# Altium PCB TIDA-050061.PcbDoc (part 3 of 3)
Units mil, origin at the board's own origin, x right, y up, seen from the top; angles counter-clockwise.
Board outline 3950.94 x 4411.21 mil, 8 copper layers (Top Layer, Layer 1, Layer 2, Layer 3, Layer 4, Layer 5, Layer 6, Bottom Layer), stack 61.2 mil thick; 178 components, 34 nets, 398 pads, 112 vias.
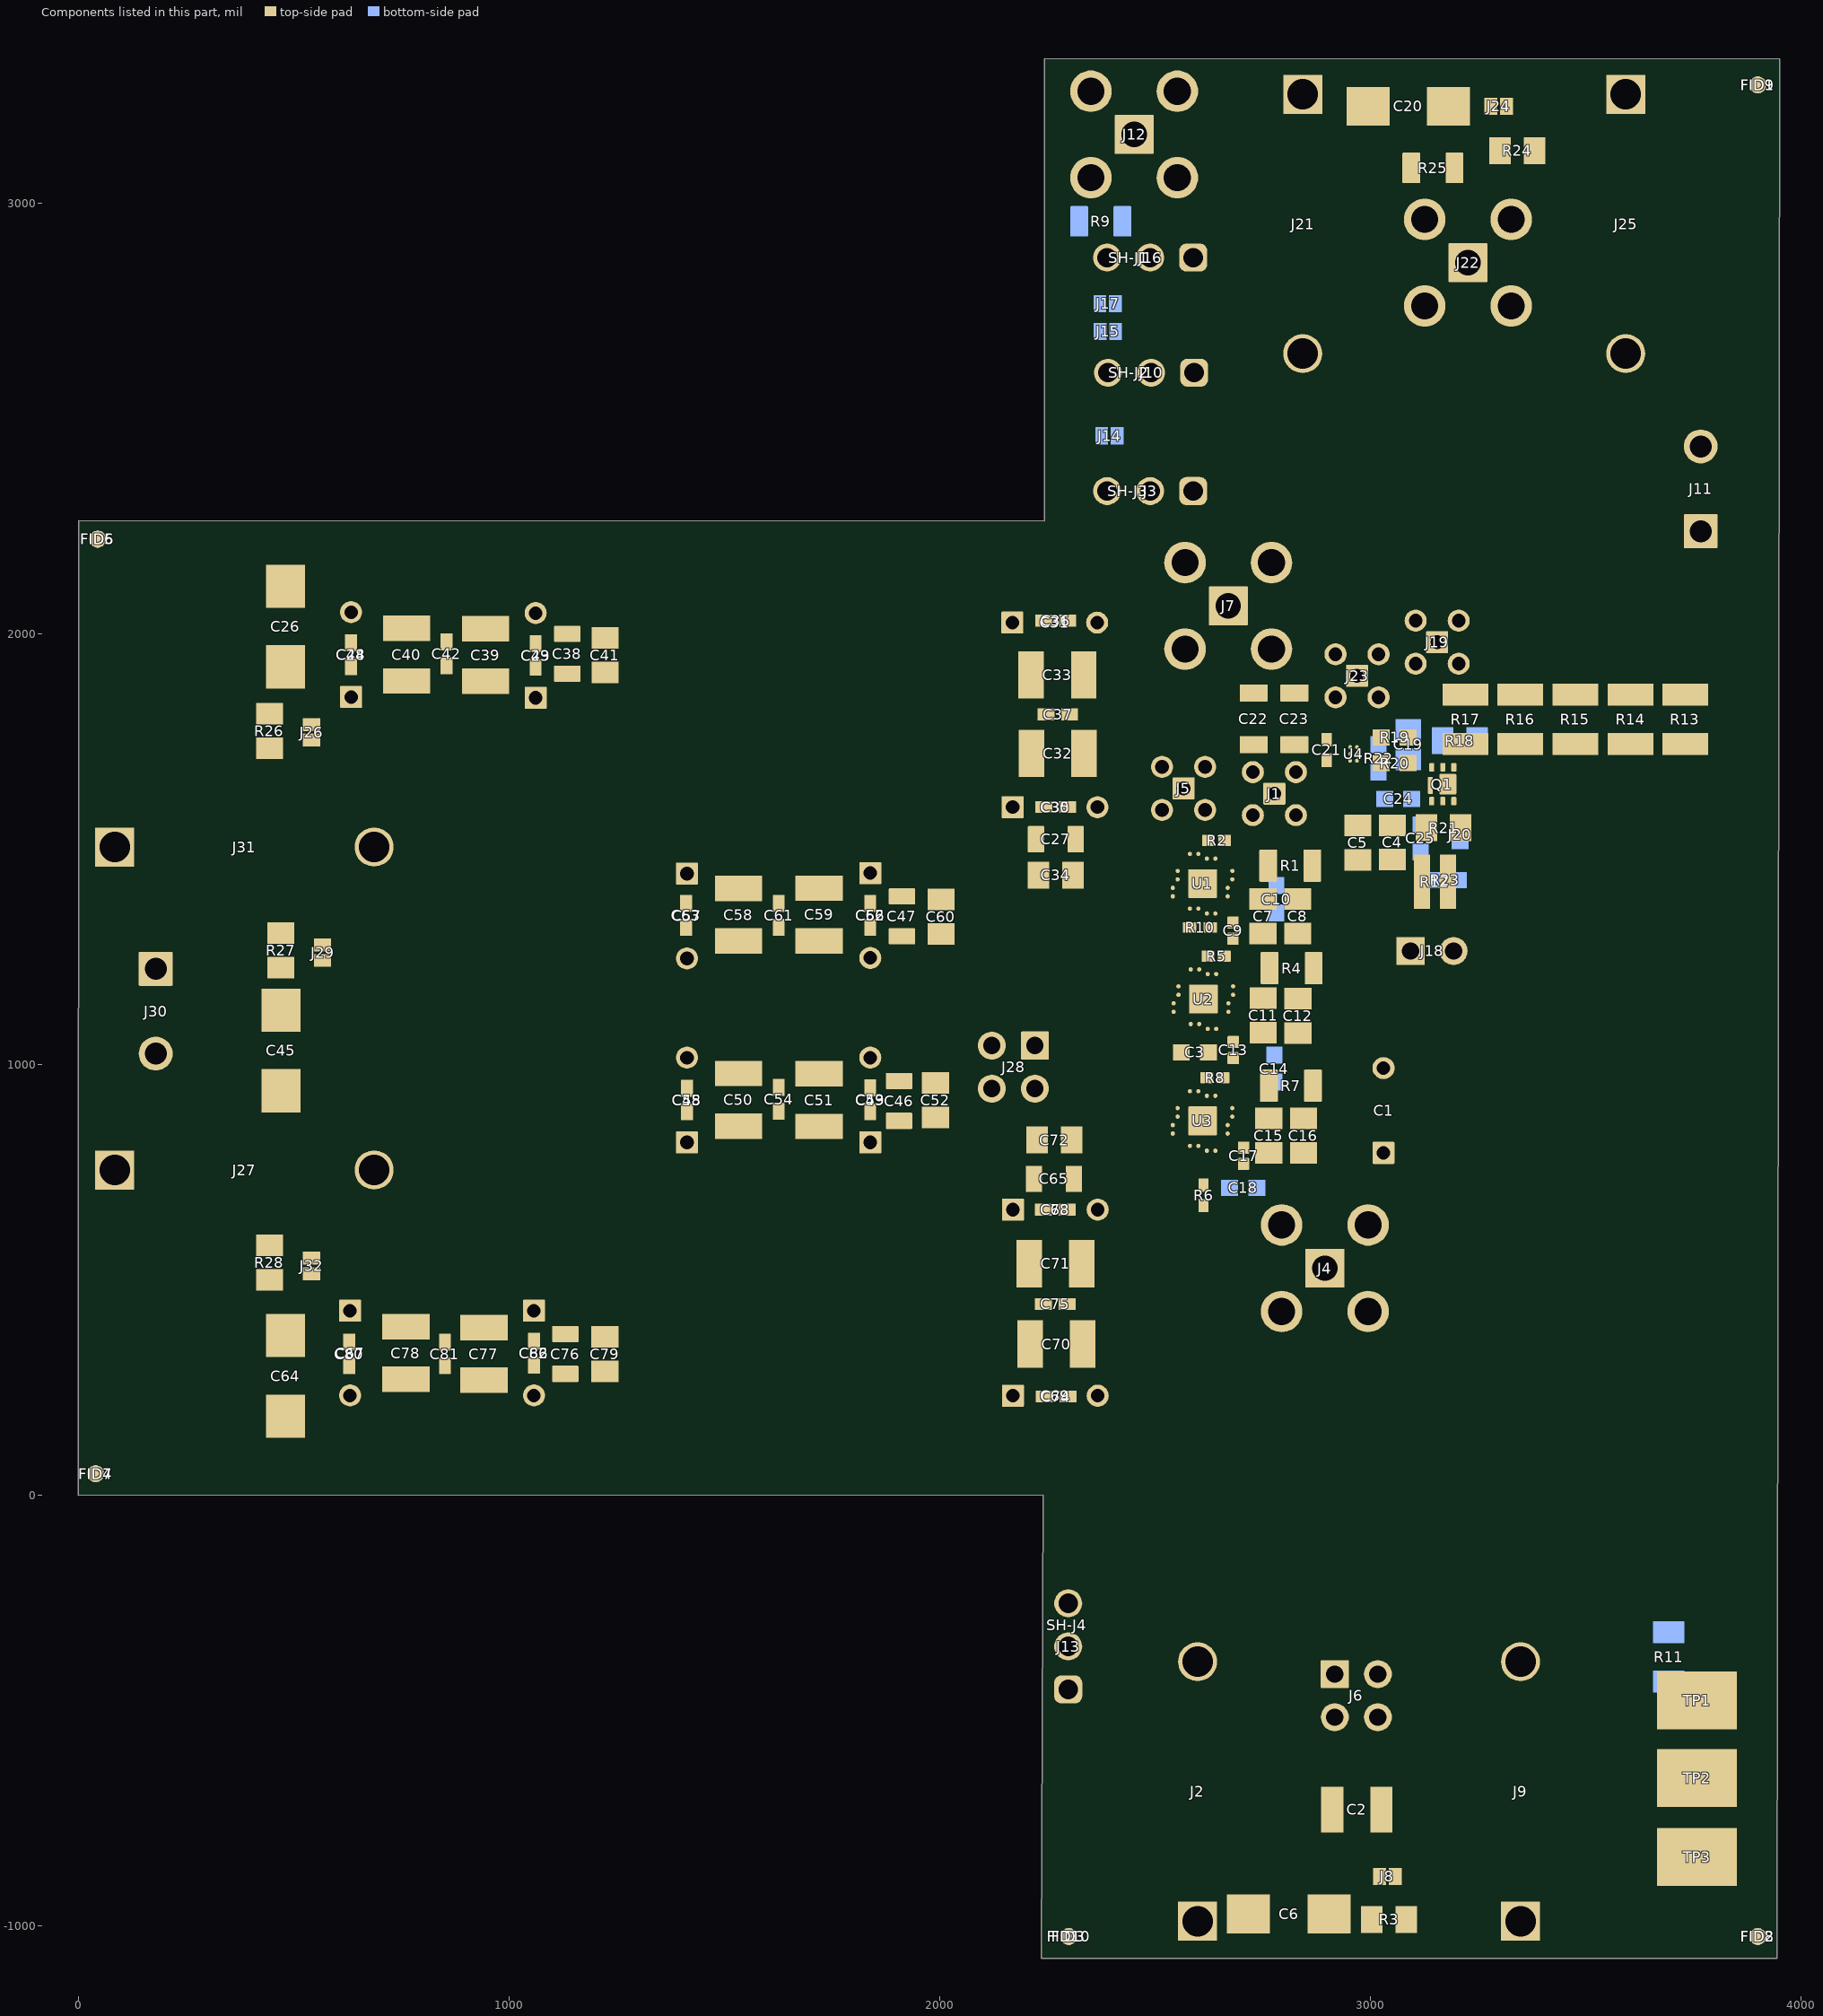
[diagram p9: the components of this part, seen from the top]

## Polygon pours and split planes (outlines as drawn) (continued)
VIN on Layer 2 "Layer 2-VIN_3" (solid, remove dead copper, pour order 143): 2272.16,-305.1 2451.36,-304.86 2451.36,765.08 2272.16,765.08 2272.16,192.87 1955.27,192.87 1953.07,190.67 1953.07,-304.74 2272.16,-304.74
GND on Layer 2 "LAYER_2_GND_P111" (solid, remove dead copper, pour order 111): 2840.11,-1075.49 2840,-1075.38 2840,-923.59 2966.86,-796.73 2966.86,-299.22 2682.6,-299.22 2682.6,1543.74 2826.56,1543.74 2828.96,1541.34 2828.96,1499.37 2842.79,1499.37 2850.84,1491.32 2850.84,914.38 2905.58,914.38 2905.58,688.01 3006.98,688.01 3013.39,681.61 3013.39,403.89 3946.77,403.89 3949.77,400.89 3946.77,397.88 3946.77,-1075.49
VIN on Layer 2 "LAYER_2_VIN_P098" (solid, remove dead copper, pour order 98): 1981.78,2274.28 1981.78,2092.11 2264.84,2092.11 2264.84,1479.74 2445.86,1479.74 2445.86,2274.27 2017.4,2274.27
GND on Layer 2 "Layer 2-GND" (solid, remove dead copper, pour order 100): 1288.87,1347.74 2266.1,1347.74 2266.1,2086.4 2268.3,2088.6 1957.05,2088.6 1957.05,1569.87 1288.78,1569.87 1288.78,1952.57 1286.22,1955.13 1286.22,1347.84 1288.78,1347.84
VOUT on Layer 2 "LAYER_2_VOUT_P061" (solid, remove dead copper, pour order 61): 3775.3,949.29 3775.3,1745.29 3780.28,1750.28 3948.35,1750.28 3948.35,946.16 3948.15,945.97 3944.83,949.29
VDD on Layer 2 "LAYER_2_VDD_P074" (solid, remove dead copper, pour order 74): 2993.02,1730.53 2635.78,1730.53 2635.78,3335.89 2993.02,3335.89
GND on Layer 2 "LAYER_2_GND_P037" (solid, remove dead copper, pour order 37): 2567.89,912.14 2761.12,912.14 2761.12,826.12 2567.89,826.12
GND on Layer 2 "LAYER_2_GND_P038" (solid, remove dead copper, pour order 38): 2569.94,1195.33 2760.62,1195.33 2760.62,1109.31 2569.94,1109.31
GND on Layer 2 "LAYER_2_GND_P039" (solid, remove dead copper, pour order 39): 2566.96,1463.8 2760.3,1463.8 2760.3,1377.77 2566.96,1377.77
VIN on Layer 6 "Layer 6-VIN" (solid, remove dead copper, pour order 156): 0,4.56 1283.03,4.56 1283.21,4.74 1283.21,4.9 2022.43,4.9 2022.43,172.97 2017.44,177.96 1283.21,177.96 1283.21,332.58 1279.18,332.58 1279.18,917.33 2019.66,917.33 2102.2,999.87 2451.36,999.87 2451.36,1346.57 1279.18,1346.57 1279.18,2089.86 2010.14,2089.86 2010.14,2259.4 2013.47,2262.72 2013.28,2262.92 1279.18,2262.92 1279.18,2269.37 202.89,2269.37 95.58,2269.94 -8.36,2269.94 -8.36,293.03 0,293.03
GND on Layer 6 "Top Layer-GND" (solid, remove dead copper, pour order 101): 1283.21,695.05 1951.48,695.05 1952.41,694.13 1952.41,203.1 2269.29,203.1 2271.5,205.3 2271.5,994.16 2096.49,994.16 2019.66,917.33 1282.52,917.33 1282.19,917.65 1282.19,917.33 1282.01,917.14 1282.01,328.03 1283.21,328.03
GND on Layer 6 "Layer 2-GND" (solid, remove dead copper, pour order 139): 1288.87,1347.74 2266.1,1347.74 2266.1,2086.4 2268.3,2088.6 1957.05,2088.6 1957.05,1569.87 1288.78,1569.87 1288.78,1952.57 1286.22,1955.13 1286.22,1347.84 1288.78,1347.84
BIAS on Layer 6 "Layer 2-BIAS" (solid, remove dead copper, pour order 110): 2236.81,-1075.32 2236.87,-1075.38 2840,-1075.38 2840,-923.59 2966.13,-797.45 2966.13,-413.68 2967.78,-415.32 2966.86,-299.22 2682.6,-299.22 2682.6,1555.75 2461.79,1555.75 2459.56,-299.22 2354,-299.22 2354,-482.81 2236.81,-600
NetJ18_2 on Layer 6 "LAYER_6_NETJ18_2_P125" (solid, remove dead copper, pour order 125): 3788.07,1793.37 3149.17,1793.37 3149.17,1503.43 3149.17,1199.6 3252.5,1199.6 3252.5,1680.47 3787.33,1680.47 3787.41,1680.39 3788.07,1681.05
VOUT on Layer 6 "Layer 2-VOUT" (solid, remove dead copper, pour order 106): 3945.01,403.89 3948.89,400.01 3949.77,400.89 3949.77,982.5 3950.93,983.67 3950.93,1745.1 3951.2,1745.36 3951.2,2345.92 3173.07,2345.92 3173.07,1792.24 3773.55,1792.24 3773.55,1008.38 3255.3,1008.38 3253.64,1010.04 3253.64,1213.87 3153.61,1213.87 3150.31,1217.18 3150.31,1499.37 3101.19,1499.37 3084.12,1516.44 2920.86,1516.44 2920.86,1519.03 2898.55,1541.34 2828.96,1541.34 2828.96,1499.37 2842.79,1499.37 2850.84,1491.32 2850.84,914.38 2905.58,914.38 2905.58,688.01 3006.98,688.01 3013.39,681.61 3013.39,403.89
GND on Layer 6 "LAYER_6_GND_P148" (solid, remove dead copper, pour order 148): 2840.11,-1075.49 2840,-1075.38 2840,-923.59 2966.86,-796.73 2966.86,-299.22 2684.06,-299.22 2684.06,1543.74 2826.56,1543.74 2828.96,1541.34 2828.96,1499.37 2842.79,1499.37 2850.84,1491.32 2850.84,914.38 2905.58,914.38 2905.58,688.01 3006.98,688.01 3013.39,681.61 3013.39,403.89 3946.77,403.89 3949.77,400.89 3946.77,397.88 3946.77,-1075.49
VDD on Layer 6 "LAYER_6_VDD_P146" (solid, remove dead copper, pour order 146): 2993.02,1730.53 2635.78,1730.53 2635.78,3335.89 2993.02,3335.89
GND on Layer 6 "LAYER_6_GND_P108" (solid, remove dead copper, pour order 108): 2243.17,3335.89 2243.17,2279.31 2446.33,2279.31 2445.86,2278.85 2445.86,1558.26 2888.43,1558.26 2931.1,1515.59 2931.95,1516.44 3084.12,1516.44 3101.19,1499.37 3104.61,1502.78 3149.17,1502.78 3149.17,1772.98 3173.07,1796.88 3173.07,2345.92 3951.2,2345.92 3953.12,2347.84 3953.12,3335.73 2993.18,3335.73 3000.72,3328.19 3000.72,1728.23 2637.43,1728.23 2635.52,1730.14 2635.78,1730.41 2635.78,3335.89
VIN on Layer 6 "LAYER_6_VIN_P142" (solid, remove dead copper, pour order 142): 1957.49,2274.29 1957.49,2092.11 2264.84,2092.11 2264.84,1479.74 2445.86,1479.74 2445.86,2274.27 2017.4,2274.27
VIN on Layer 6 "Layer 2-VIN_3" (solid, remove dead copper, pour order 97): 2271.5,-292.67 2450.69,-292.44 2450.69,765.08 2271.5,765.08 2271.5,205.3 1954.61,205.3 1952.41,203.09 1952.41,-292.31 2271.5,-292.31
GND on Layer 6 "LAYER_6_GND_P113" (solid, remove dead copper, pour order 113): 2566.96,1463.8 2711.1,1463.8 2711.1,1377.77 2566.96,1377.77
VOUT on Layer 6 "LAYER_6_VOUT_P036" (solid, remove dead copper, pour order 36): 3775.3,949.29 3775.3,1745.29 3780.28,1750.28 3948.35,1750.28 3948.35,946.16 3948.15,945.97 3944.83,949.29
GND on Layer 6 "LAYER_6_GND_P090" (solid, remove dead copper, pour order 90): 2567.89,912.14 2702.6,912.14 2702.6,826.12 2567.89,826.12
GND on Layer 6 "LAYER_6_GND_P083" (solid, remove dead copper, pour order 83): 2570.03,1195.33 2712.51,1195.33 2712.51,1109.31 2570.03,1109.31
VIN on Layer 4 "Layer 4-VIN" (solid, remove dead copper, pour order 155): 0,4.56 1283.03,4.56 1283.21,4.74 1283.21,4.9 2022.43,4.9 2022.43,172.97 2017.44,177.96 1283.21,177.96 1283.21,332.58 1279.18,332.58 1279.18,917.33 1950.48,917.33 1950.48,1345.26 1279.18,1345.26 1279.18,2089.86 2010.14,2089.86 2010.14,2259.4 2013.47,2262.72 2013.28,2262.92 1279.18,2262.92 1279.18,2269.37 202.89,2269.37 95.58,2269.94 -8.36,2269.94 -8.36,261.1 0,261.1
VOUT on Layer 4 "LAYER_4_VOUT_P153" (solid, remove dead copper, pour order 153): 3147.57,1527.35 3153.61,1521.31 3140.22,1507.91 3140.22,1156.41 3070.1,1156.41 2885.74,1340.78 2885.74,1527.35
VOUT on Layer 4 "LAYER_4_VOUT_P152" (solid, remove dead copper, pour order 152): 3173.07,2345.92 3951.2,2345.92 3951.2,427.1 3805.06,427.1 3567.04,665.12 3567.04,1010.13 3771.8,1010.13 3773.55,1008.38 3773.55,1677.57 3786.87,1677.57 3793.52,1684.22 3793.52,1796.55 3168.76,1796.55 3166.97,1798.33 3173.07,1804.43
VDD on Layer 4 "LAYER_4_VDD_P138" (solid, remove dead copper, pour order 138): 3035.27,3335.73 3035.27,2515.65 2651.41,2515.65 2651.41,3335.73 2651.41,2515.65 2651.41,3335.73
GND on Layer 4 "Layer 4-GND" (solid, remove dead copper, pour order 137): 2840,-1075.38 2840.09,-1075.47 3763.37,-1075.47 3763.37,-850 3653.37,-740 3650,-740 3650,250 3567.04,332.96 3271.63,332.96 3271.63,829.52 2882.25,1218.9 2880.17,1218.9 2880.17,1546.75 2437.86,1543.64 2437.86,-289.22 2963.95,-289.22 2966.13,-291.4 2966.13,-797.45 2840,-923.59
GND on Layer 4 "LAYER_4_GND_P130" (solid, remove dead copper, pour order 130): 3950.91,3333.52 3948.7,3335.73 3035.27,3335.73 3035.27,2515.65 2651.41,2515.65 2651.41,3335.73 2651.24,3335.89 2243.17,3335.89 2243.17,2939.4 2516.63,2939.4 2516.63,1561.4 2491.63,1536.4 2493.35,1534.68 3146.92,1534.68 3146.92,1787.35 3151.75,1792.19 3168.37,1792.19 3168.37,2348.62 3168.76,2349.01 3169.94,2347.84 3953.12,2347.84 3953.12,3335.73
BIAS on Layer 4 "Layer 2-BIAS" (solid, remove dead copper, pour order 126): 2236.81,-1075.32 2236.87,-1075.38 2840,-1075.38 2840,-923.59 2966.13,-797.45 2966.13,-413.68 2967.78,-415.32 2966.86,-299.22 2736.19,-299.22 2459.56,-299.22 2354,-299.22 2354,-482.81 2236.81,-600
NetJ18_2 on Layer 4 "LAYER_4_NETJ18_2_P002" (solid, remove dead copper, pour order 2): 3789.21,1792.24 3150.31,1792.24 3150.31,1502.29 3150.31,1157.99 3253.64,1157.99 3253.64,1679.33 3788.47,1679.33 3788.55,1679.25 3789.21,1679.91
GND on Layer 4 "Layer 1-GND" (solid, remove dead copper, pour order 124): 1283.15,327.97 1283.21,328.03 1283.21,695.05 1951.48,695.05 1952.41,694.13 1952.41,0.35 2256.88,0.35 2256.88,2269.03 1957.49,2269.03 1957.49,1568.21 1289.22,1568.21 1288.29,1569.13 1288.29,1953.47 1283.15,1953.47
VOUT on Layer 4 "LAYER_4_VOUT_P055" (solid, remove dead copper, pour order 55): 3775.3,949.29 3775.3,1745.29 3780.28,1750.28 3948.35,1750.28 3948.35,946.16 3948.15,945.97 3944.83,949.29
GND on Layer 4 "LAYER_4_GND_P091" (solid, remove dead copper, pour order 91): 2566.58,1463.66 2652.6,1463.66 2652.6,1377.64 2566.58,1377.64
GND on Layer 4 "LAYER_4_GND_P084" (solid, remove dead copper, pour order 84): 2569.94,1195.33 2655.96,1195.33 2655.96,1109.31 2569.94,1109.31
GND on Layer 4 "LAYER_4_GND_P078" (solid, remove dead copper, pour order 78): 2567.58,912.25 2653.6,912.25 2653.6,826.22 2567.58,826.22
VOUT on Layer 1 "LAYER_1_VOUT_P034" (solid, remove dead copper, pour order 34): 3775.3,949.29 3775.3,1745.29 3780.28,1750.28 3948.35,1750.28 3948.35,946.16 3948.15,945.97 3944.83,949.29
VIN on Layer 1 "Top Layer-VIN_1" (solid, remove dead copper, pour order 80): -3.81,1951.83 1282.1,1951.83 1283.74,1953.47 1283.74,2089.86 2014.7,2089.86 2014.7,2259.4 2018.02,2262.72 2017.83,2262.92 1283.74,2262.92 1283.74,2269.37 207.44,2269.37 100.13,2269.94 -3.81,2269.94
GND on Layer 1 "Layer 1-GND" (solid, remove dead copper, pour order 87): 0.8,327.97 1283.15,327.97 1283.21,328.03 1283.21,695.05 1951.48,695.05 1952.41,694.13 1952.41,176.33 2014.52,176.33 2022.43,168.41 2022.43,0.35 2240.16,0.35 2236.87,-2.94 2236.87,-1075.38 3767.43,-1075.38 3767.34,-1075.47 3767.36,-1075.49 3946.77,-1075.49 3946.77,944.58 3947.17,944.98 3775.3,944.98 3775.3,1753.3 3945.33,1753.3 3948.35,1750.28 3953.12,1755.05 3953.12,3335.73 2243.33,3335.73 2243.21,3335.85 2243.21,2269.07 2018.23,2269.07 2019.25,2268.04 2019.25,2089.86 1957.49,2089.86 1957.49,1568.21 1289.22,1568.21 1288.29,1569.13 1288.29,1953.47 0.8,1953.47
VIN on Layer 1 "Layer 1-VIN_3" (solid, remove dead copper, pour order 70): 0,0 1283.03,0 1283.21,0.18 1283.21,0.35 2022.43,0.35 2022.43,168.41 2017.44,173.4 1283.21,173.4 1283.21,328.03 0,328.03
GND on Bottom Layer "Layer 1-GND" (solid, remove dead copper, pour order 112): 0.66,327.9 1283.01,327.9 1283.07,327.96 1283.07,694.98 1951.34,694.99 1952.26,694.06 1952.26,176.26 2014.37,176.26 2022.29,168.34 2022.29,0.28 2240.01,0.28 2236.72,-3.01 2236.72,-1075.45 3767.29,-1075.45 3767.2,-1075.54 3767.21,-1075.56 3946.62,-1075.56 3946.62,944.51 3947.03,944.91 3775.15,944.91 3775.15,1753.23 3945.18,1753.23 3948.2,1750.21 3952.97,1754.98 3952.97,3335.66 2243.19,3335.66 2243.06,3335.78 2243.06,2269 2018.08,2269 2019.11,2267.97 2019.11,2089.8 1957.34,2089.8 1957.34,1568.14 1289.07,1568.14 1288.15,1569.06 1288.15,1953.4 0.66,1953.4
VOUT on Bottom Layer "BOTTOM_LAYER_VOUT_P056" (solid, remove dead copper, pour order 56): 3775.3,949.29 3775.3,1745.29 3780.28,1750.28 3948.35,1750.28 3948.35,946.16 3948.15,945.97 3944.83,949.29
VOUT on Bottom Layer "BOTTOM_LAYER_VOUT_P073" (solid, remove dead copper, pour order 73): 3775.3,949.29 3775.3,1745.29 3780.28,1750.28 3948.35,1750.28 3948.35,946.16 3948.15,945.97 3944.83,949.29
VIN on Bottom Layer "Layer 1-VIN_3" (solid, remove dead copper, pour order 86): 0,4.56 1283.03,4.56 1283.21,4.74 1283.21,4.9 2022.43,4.9 2022.43,172.97 2017.44,177.96 1283.21,177.96 1283.21,332.58 0,332.58
VIN on Bottom Layer "Top Layer-VIN_1" (solid, remove dead copper, pour order 85): -8.36,1951.83 1277.54,1951.83 1279.18,1953.47 1279.18,2089.86 2010.14,2089.86 2010.14,2259.4 2013.47,2262.72 2013.28,2262.92 1279.18,2262.92 1279.18,2269.37 202.89,2269.37 95.58,2269.94 -8.36,2269.94
VIN on Layer 3 "Top Layer-VIN_2" (solid, remove dead copper, pour order 123): 1013.76,917.33 1950.48,917.33 1950.48,1345.26 763.47,1345.26 543.42,1125.21 0.8,1125.21 0.8,600 1009.95,600 1009.95,913.52
GND on Layer 3 "Layer 1-GND" (solid, remove dead copper, pour order 119): 0.8,327.97 1283.15,327.97 1283.21,328.03 1283.21,695.05 1951.48,695.05 1952.41,694.13 1952.41,176.33 2014.52,176.33 2022.43,168.41 2022.43,0.35 2240.16,0.35 2236.87,-2.94 2236.87,-1075.38 3767.43,-1075.38 3767.34,-1075.47 3767.36,-1075.49 3946.77,-1075.49 3946.77,944.58 3947.17,944.98 3775.3,944.98 3775.3,1753.3 3945.33,1753.3 3948.35,1750.28 3953.12,1755.05 3953.12,3335.73 2243.33,3335.73 2243.21,3335.85 2243.21,2269.07 2018.23,2269.07 2019.25,2268.04 2019.25,2089.86 1957.49,2089.86 1957.49,1568.21 1289.22,1568.21 1288.29,1569.13 1288.29,1953.47 0.8,1953.47
GND on Layer 3 "LAYER_3_GND_P118" (solid, remove dead copper, pour order 118): 2567.67,912.85 2653.69,912.85 2653.69,826.83 2567.67,826.83
GND on Layer 3 "LAYER_3_GND_P117" (solid, remove dead copper, pour order 117): 2569.51,1195.67 2655.54,1195.67 2655.54,1109.65 2569.51,1109.65
GND on Layer 3 "LAYER_3_GND_P076" (solid, remove dead copper, pour order 76): 2566.96,1463.8 2652.98,1463.8 2652.98,1377.77 2566.96,1377.77
VOUT on Layer 3 "LAYER_3_VOUT_P015" (solid, remove dead copper, pour order 15): 3775.3,949.29 3775.3,1745.29 3780.28,1750.28 3948.35,1750.28 3948.35,946.16 3948.15,945.97 3944.83,949.29
VIN on Layer 3 "Top Layer-VIN_1" (solid, remove dead copper, pour order 81): -6.09,1951.83 1279.82,1951.83 1281.46,1953.47 1281.46,2089.86 2012.42,2089.86 2012.42,2259.4 2015.75,2262.72 2015.55,2262.92 1281.46,2262.92 1281.46,2269.37 205.16,2269.37 97.86,2269.94 -6.09,2269.94
VIN on Layer 3 "Layer 1-VIN_3" (solid, remove dead copper, pour order 75): 0,4.56 1283.03,4.56 1283.21,4.74 1283.21,4.9 2022.43,4.9 2022.43,172.97 2017.44,177.96 1283.21,177.96 1283.21,332.58 0,332.58
GND on Layer 5 "Layer 1-GND" (solid, remove dead copper, pour order 122): 0.8,327.97 1283.15,327.97 1283.21,328.03 1283.21,695.05 1951.48,695.05 1952.41,694.13 1952.41,176.33 2014.52,176.33 2022.43,168.41 2022.43,0.35 2240.16,0.35 2236.87,-2.94 2236.87,-1075.38 3767.43,-1075.38 3767.34,-1075.47 3767.36,-1075.49 3946.77,-1075.49 3946.77,944.58 3947.17,944.98 3775.3,944.98 3775.3,1753.3 3945.33,1753.3 3948.35,1750.28 3953.12,1755.05 3953.12,3335.73 2243.33,3335.73 2243.21,3335.85 2243.21,2269.07 2018.23,2269.07 2019.25,2268.04 2019.25,2089.86 1957.49,2089.86 1957.49,1568.21 1289.22,1568.21 1288.29,1569.13 1288.29,1953.47 0.8,1953.47
VIN on Layer 5 "Top Layer-VIN_2" (solid, remove dead copper, pour order 121): 1013.76,917.33 1950.48,917.33 1950.48,1345.26 763.47,1345.26 543.42,1125.21 0.8,1125.21 0.8,600 1009.95,600 1009.95,913.52
GND on Layer 5 "LAYER_5_GND_P116" (solid, remove dead copper, pour order 116): 2566.96,1463.8 2652.98,1463.8 2652.98,1377.77 2566.96,1377.77
GND on Layer 5 "LAYER_5_GND_P115" (solid, remove dead copper, pour order 115): 2567.82,912.07 2653.84,912.07 2653.84,826.05 2567.82,826.05
GND on Layer 5 "LAYER_5_GND_P114" (solid, remove dead copper, pour order 114): 2569.83,1195.31 2655.85,1195.31 2655.85,1109.28 2569.83,1109.28
VOUT on Layer 5 "LAYER_5_VOUT_P089" (solid, remove dead copper, pour order 89): 3775.3,949.29 3775.3,1745.29 3780.28,1750.28 3948.35,1750.28 3948.35,946.16 3948.15,945.97 3944.83,949.29
VIN on Layer 5 "Top Layer-VIN_1" (solid, remove dead copper, pour order 63): 0.75,1951.83 1286.65,1951.83 1288.29,1953.47 1288.29,2089.86 2019.25,2089.86 2019.25,2259.4 2022.58,2262.72 2022.39,2262.92 1288.29,2262.92 1288.29,2269.37 212,2269.37 104.69,2269.94 0.75,2269.94
VIN on Layer 5 "Layer 1-VIN_3" (solid, remove dead copper, pour order 77): 0,4.56 1283.03,4.56 1283.21,4.74 1283.21,4.9 2022.43,4.9 2022.43,172.97 2017.44,177.96 1283.21,177.96 1283.21,332.58 0,332.58

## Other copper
Top Layer:
  rectangle net NetC15_1: 2710.37,916.45 2745.93,971.03
  rectangle net NetC11_1: 2716.03,1188.21 2746.95,1260.86
  rectangle net NetC7_1: 2704.45,1426.17 2745.12,1499.13
  rectangle net VIN: 2472.35,1462.96 2520.75,1512.92
  rectangle net GND: 2472.79,1528.34 2521.19,1578.3
  region net GND: 2494.37,970.3 2494.37,1033.1 2459.42,1033.1 2459.42,970.3
  rectangle net GND: 2445.24,949.16 2508.04,996.76
  rectangle net VIN: 2445.96,873.77 2494.37,923.73
  rectangle net VIN: 2460,1087.19 2508.4,1137.15
  rectangle net GND: 2445.6,1003.89 2508.4,1051.51
  rectangle net VOUT: 3805.94,950.36 3927.4,1745.29
  region net VIN: 2018.19,2120.51 2018.19,2241.97 1223.26,2241.97 1223.26,2120.51
  region net VIN: 1222.51,142.76 1222.51,21.3 2017.44,21.3 2017.44,142.76
Bottom Layer:
  rectangle net GND: 3790,-258.3 3861.5,421.7
  rectangle net GND: 3647.11,-99.75 3718.61,240.25
  region net VIN: 1222.51,142.76 1222.51,21.3 2017.44,21.3 2017.44,142.76
  region net VIN: 2020.31,2121.64 2020.31,2243.1 1225.38,2243.1 1225.38,2121.64
  rectangle net VOUT: 3805.94,950.36 3927.4,1745.29
  rectangle net GND: 3695.79,-783.32 3767.29,-653.32
  rectangle net GND: 3837.27,-855.22 3864.77,-595.22

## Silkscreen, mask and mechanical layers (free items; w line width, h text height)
Top Overlay:
  lines w10: 753.37,50.1 1176.69,50.1 1153.54,63.68 ; 776.25,2152.27 1184.5,2152.27 1161.35,2165.85 ; 1153.54,40.1 1177.17,50.1 ; 1161.35,2142.27 1184.97,2152.27 ; 2956.41,2215.11 2999.75,2053.46 ; 3815.19,897.6 3828.77,920.75 ; 3828.56,523.29 3828.56,921.32 ; 3828.77,921.22 3842.3,897.6 ; 2758.79,2584.68 3686.35,2584.68 3686.35,3331.31 2758.79,3331.31 2758.79,2584.68 ; 3077.92,2294.61 3213.57,2294.78 3213.02,2412.58 3107.92,2412.58 3078.35,2372.82 3077.92,2294.61
  text "EN_3" at 2263.25,2962.07 h40 r270
  text "EN_2" at 2266.54,2684.83 h40 r270
  text "Gate Driver" at 2901.24,2613.54 h60
  text "GND" at 3726.22,2584.68 h60
  text "EN_1" at 2266.54,2423.03 h40 r270
  text "VIN" at 2662.31,2227.14 h40
  text "Iin 1 Loop" at 776.25,2165.85 h40
  text "VOUT" at 3841.17,2115.41 h60 r270
  text "Vds" at 3019.42,2076.86 h40
  text "Vgs" at 2842.57,1988.64 h40
  text "VIN" at 2517.07,1725.75 h40
  text "VOUT" at 2858.59,1597.25 h40
  text "GND" at 187.16,1568.21 h60 r270
  text "6 Vdc / 15 Adc" at 794.68,1054.68 h60
  text "Iout Loop" at 3843.1,881.03 h40 r270
  text "VIN" at 240,830 h60 r270
  text "VOUT" at 2541.4,494.76 h40
  text "'.PRJ_Number'.PCB_Rev" at 3828.56,398.27 h108.27 r270
  text "Iin 3 Loop" at 753.37,54.68 h40
  text "TIDA-050061" at 2348.69,40.46 h60
  text "GND" at 3264.52,-310.64 h60
  text "VBIAS / 6 Vdc" at 2503.37,-515.32 h60 r270
  text "LDO 1 PG" at 3321.45,-546.76 h40
  text "LDO 2 PG" at 3315.04,-724.55 h40
  text "LDO 3 PG" at 3303.12,-909.95 h40
Bottom Overlay:
  lines w10: 2821.61,1040.48 2894.74,1100 ; 2899.16,1792.19 2969.42,1769.19 ; 3046.42,1339.21 3150.58,1388.34
  text "EN_3" at 2339.89,2878.83 h40 r90
  text "EN_2" at 2630.41,2684.83 h40
  text "EN_1" at 2633.06,2450 h40
Bottom Solder:
  rectangle: 2491.63,757.4 2741.63,1507.4
M1 Board Outline:
  lines w10: 0,0 2240.16,0.35 2236.81,-1070.97 ; 0,0.24 0.8,2262.93 2243.13,2261.93 2243.17,3335.89 3950.94,3335.56 3944.58,-1075.28 2236.81,-1075.32
M2 Board Dimensions:
  rectangle: -2093.9,-1787.58 -1968.9,-1662.58
  rectangle: -1968.9,-1912.58 -1593.9,-1787.58
  lines w7: -2093.9,-1787.58 -1093.9,-1787.58 ; -1968.9,-1912.58 -1968.9,-1662.58 ; -1843.9,-1912.58 -1843.9,-1662.58 ; -1593.9,-1912.58 -1593.9,-1662.58 ; -1343.9,-1912.58 -1343.9,-1662.58 ; -2093.9,-1912.58 -1093.9,-1912.58 -1093.9,-1662.58 -2093.9,-1662.58 -2093.9,-1912.58
M5 Assembly Top:
  lines w10: -2385.9,-2442.75 4214.1,-2442.75 ; -2385.9,-2239.41 4216.1,-2239.41 ; -2385.9,-2036.08 -2385.9,-2646.08 1619.1,-2646.08 4216.1,-2646.08 4216.1,-2036.08 -2385.4,-2036.08 -2385.4,-2646.08 -809.9,-2646.08 ; 79.1,-2646.08 79.1,-2036.08 ; 1346.1,-2239.41 1346.1,-2036.08 ; 2186.1,-2239.41 2186.1,-2036.08 ; 2808.1,-2652.58 2808.1,-2449.75
  text "COMPONENTS MARKED 'DNP' SHOULD NOT BE POPULATED." at -940.4,-1831.08 h60
  text "ASSEMBLY VARIANT:" at -940.9,-1946.58 h60
  text ".VariantName" at 95.1,-1946.58 h60
  text "PCB VIEWED FROM TOP SIDE" at -2322.4,-2168.25 h60
  text "BOARD #:" at 154.1,-2168.25 h60
  text ".PRJ_Number" at 699.6,-2168.25 h60
  text "REV:" at 1544.1,-2168.25 h60
  text ".PCB_Rev" at 1835.6,-2168.25 h60
  text "SVN REV:" at 2382.1,-2168.25 h60
  text ".VersionControl_RevNumber" at 2888.1,-2168.25 h60
  text "TID #:" at 154.1,-2371.58 h60
  text ".TID" at 699.6,-2371.58 h60
  text "PLOT NAME =" at -2322.4,-2576.92 h60
  text ".plot_File_Name" at -1516.9,-2576.92 h60
  text "GENERATED    :" at 156.1,-2576.92 h60
  text ".Print_Date" at 1025.6,-2576.92 h60
  text ".Print_Time" at 1754.6,-2576.92 h60
  text "TEXAS INSTRUMENTS" at 3019.1,-2576.92 h60
M6 Assembly Bottom:
  lines w10: -2386.4,-2239.91 4215.6,-2239.91 ; -2384.4,-2443.25 4215.6,-2443.25 ; -978.4,-2653.08 -978.4,-2450.25 ; -356.4,-2239.91 -356.4,-2036.58 ; 483.6,-2239.91 483.6,-2036.58 ; 1750.6,-2646.58 1750.6,-2036.58 ; 2639.6,-2646.58 4215.1,-2646.58 4215.1,-2036.58 -2386.4,-2036.58 -2386.4,-2646.58 210.6,-2646.58 4215.6,-2646.58 4215.6,-2036.58
  text "COMPONENTS MARKED 'DNP' SHOULD NOT BE POPULATED." at 4008.1,-1830.58 h60
  text ".VariantName" at 2964.1,-1946.58 h60
  text "ASSEMBLY VARIANT:" at 4003.1,-1946.58 h60
  text ".VersionControl_RevNumber" at -1058.4,-2168.75 h60
  text "SVN REV:" at -552.4,-2168.75 h60
  text ".PCB_Rev" at -5.9,-2168.75 h60
  text "REV:" at 285.6,-2168.75 h60
  text ".PRJ_Number" at 1130.1,-2168.75 h60
  text "BOARD #:" at 1675.6,-2168.75 h60
  text "PCB VIEWED FROM BOTTOM SIDE" at 4152.1,-2168.75 h60
  text ".TID" at 1130.1,-2372.08 h60
  text "TID #:" at 1675.6,-2372.08 h60
  text "TEXAS INSTRUMENTS" at -1189.4,-2577.42 h60
  text ".Print_Time" at 75.1,-2577.42 h60
  text ".Print_Date" at 804.1,-2577.42 h60
  text "GENERATED    :" at 1673.6,-2577.42 h60
  text ".plot_File_Name" at 3346.6,-2577.42 h60
  text "PLOT NAME =" at 4152.1,-2577.42 h60
M9 Title Sheet:
  drawing of 57 lines, arcs and shapes, not listed
  text "1" at -1354.06,6523.92 h70
  text "2" at 1141.6,6523.92 h70
  text "3" at 3630.95,6523.92 h70
  text "4" at 6137.62,6523.92 h70
  text "5" at 8636.6,6523.92 h70
  text "6" at 11141.6,6523.92 h70
  text "A" at -2510.4,5380.92 h70
  text "A" at 12289.6,5380.92 h70
  text "B" at -2510.4,3000.92 h70
  text "B" at 12289.6,3000.92 h70
  text "C" at -2510.4,625.92 h70
  text "C" at 12289.6,625.92 h70
  text "PROJECT TITLE:" at 9249.6,-1235.08 h45
  text ".PRJ_Title" at 9299.6,-1368.41 h70
  text "DESIGNED FOR:" at 9249.6,-1536.08 h45
  text ".PRJ_Customer" at 9299.6,-1676.08 h70
  text "D" at -2510.4,-1744.08 h70
  text "D" at 12289.6,-1744.08 h70
  text "FILE NAME:" at 9249.6,-1836.08 h45
  text ".PCB_File_Name_No_Path" at 9299.6,-1956.08 h70
  text "Texas Instruments (TI) and/or its licensors do not warrant the accuracy or completeness of this specification" at 4280.1,-2117.92 h45
  text "ENGINEER:" at 9249.6,-2126.08 h45
  text "LAYOUT BY:" at 10754.6,-2126.08 h45
  text "or any information contained therein. TI and/or its licensors do not warrant that this design will meet" at 4235.12,-2230.59 h45
  text ".PRJ_Engineer" at 9299.6,-2281.07 h70
  text ".PCB_Layout" at 10805.1,-2281.07 h70
  text "the specifications, will be suitable for your application or fit for any particular purpose, or will operate in" at 4235.12,-2343.25 h45
  text ".Layer_Name" at -1516.9,-2371.07 h60
  text "ALTIUM DESIGNER VERSION:" at 10754.6,-2436.08 h45
  text "an implementation. TI and/or its licensors do not warrant that the design is production worthy. You should" at 4235.12,-2455.92 h45
  text "completely validate and test your design implementation to confirm the system functionality for your application." at 4280.1,-2568.58 h45
  text ".print_Scale" at 9299.6,-2569.41 h70
  text ".Application_BuildNumber" at 10805.1,-2569.41 h70
  text "1" at -1354.06,-2776.08 h70
  text "2" at 1141.6,-2776.08 h70
  text "3" at 3630.95,-2776.08 h70
  text "4" at 6137.62,-2776.08 h70
  text "5" at 8636.6,-2776.08 h70
  text "6" at 11141.6,-2776.08 h70
M10 Fab Notes:
  drawing of 186 lines, arcs and shapes, not listed
  text "DESIGN INFORMATION" at 10281.5,4867.19 h60
  text "MIN. TRACK WIDTH:" at 9636.94,4735.06 h60
  text "8" at 10733.19,4735.06 h60
  text "MIL" at 10887.94,4735.06 h60
  text "MIN. CLEARANCE:" at 9636.94,4610.94 h60
  text "0.2" at 10673.19,4610.94 h60
  text "mm" at 10887.94,4610.94 h60
  text "MIN. VIA PAD SIZE:" at 9636.94,4486.81 h60
  text "20" at 10703.2,4486.81 h60
  text "MIL" at 10887.94,4486.81 h60
  text "0.05mm (2MIL)" at 10331.94,4356.91 h60
  text "MINIMUM ANNULAR RING" at 9307.71,4348.69 h60
  text "EXTERNAL" at 11039.94,4348.69 h60
  text "PER" at 9507.71,4238.56 h60
  text "IPC-D-275 CLASS 2 LEVEL C" at 9727.71,4238.56 h60
  text "MIL, HOLES" at 11215.94,4138.08 h60
  text "+/-" at 10823.49,4129.5 h60
  text "+/-" at 11677.49,4129.5 h60
  text "REGISTRATION TOLERANCES:" at 9307.71,4128.43 h60
  text "METAL" at 10507.49,4128.43 h60
  text "5" at 11083.69,4128.43 h60
  text "3" at 11916.69,4128.43 h60
  text "MIL" at 12032.94,4128.43 h60
  text "HOLE SIZE TOLERANCE (UNLESS OTHERWISE SPECIFIED):" at 9307.71,4030.12 h60
  text "+/-" at 11677.49,4027.24 h60
  text "3" at 11916.69,4026.18 h60
  text "MIL" at 12032.94,4026.18 h60
  text "MATERIAL:" at 9232.94,3888.53 h60
  text "FR-4 High Tg" at 10219.39,3760.01 h60
  text "X" at 10074.95,3752.02 h60
  text "FR-408" at 9653.95,3747.5 h60
  text "OTHER" at 11141.94,3747.5 h60
  text "+/-" at 3436.94,3746 h60
  text "0.25mm" at 3352.64,3641 h60
  text "62 MIL (1.6mm) +/-10%" at 9974.05,3604.47 h60
  text "X" at 9853.95,3602.02 h60
  text "THICKNESS:" at 9307.71,3596.25 h60
  text "OTHER" at 11258.94,3596.25 h60
  text "TOLERANCE:" at 9307.71,3457.94 h60
  text "X" at 10155.95,3457.94 h60
  text "ANSI IPC-6012 TYPE 3 CLASS 2" at 10333.96,3457.94 h60
  text "BOW & TWIST:" at 9307.71,3318.56 h60
  text "X" at 10155.95,3318.56 h60
  text "ANSI IPC-6012 TYPE 3 CLASS 2" at 10333.96,3318.56 h60
  text "DRILLING:" at 9238.41,3191.24 h60
  text "NC_DRILL FILES" at 10999.41,3086.05 h60
  text "REFERENCE:" at 9313.18,3082.12 h60
  text "X" at 9970.42,3082.02 h60
  text "AS SHOWN" at 10148.41,3082.12 h60
  text "X" at 10871.42,3082.12 h60
  text "OTHER" at 11297.41,2939.86 h60
  text "PTH COPPER THICKNESS:" at 9312.86,2936.34 h60
  text "X" at 10452.1,2936.34 h60
  text "20-30 um" at 10580.09,2936.34 h60
  text "BOARD FINISH:" at 9222.94,2808.74 h60
  text "SILKSCREEN:" at 9378.17,2698.61 h60
  text "X" at 10335.95,2698.61 h60
  text "TOP" at 10452.94,2698.61 h60
  text "X" at 10845.95,2698.61 h60
  text "BOTTOM" at 10963.94,2698.61 h60
  text "BLACK" at 10648.44,2544.5 h60
  text "PRIMARY SILKSCREEN COLOR:" at 9378.17,2543.42 h60
  text "+/- 0.25mm" at 1328.49,2509.17 h60
  text "ALTIUM LAYER:" at 9925.48,2424.5 h60
  text "OVERLAY" at 10578.44,2424.5 h60
  text "WHITE" at 10638.44,2206.64 h60
  text "SECOND SILKSCREEN COLOR:" at 9368.17,2205.56 h60
  text "ALTIUM LAYERS:" at 9910,2075 h60
  text "MECHANICAL 20 and MECHANICAL 25" at 10598.44,2074.5 h60
  text "#CC0000" at 11516.91,1844.5 h60
  text "GREEN" at 10563.94,1839.98 h60
  text "X" at 11045.48,1839.98 h60
  text "OTHER" at 11181.94,1839.98 h60
  text "SOLDER RESIST COLOR:" at 9358.17,1833.11 h60
  text "+/-" at -236,1754.35 h60 r90
  text "X" at 10445.95,1685.72 h60
  text "MATTE" at 10563.94,1685.72 h60
  text "SEMI-GLOSS" at 11181.48,1685.09 h60
  text "0.25mm" at -146,1646 h60 r90
  text "IMMERSION GOLD (ENIG)" at 10303.94,1532.95 h60
  text "ENEPIG" at 11641.49,1525.73 h60
  text "SURFACE FINISH:" at 9242.94,1524.73 h60
  text "X" at 10125.95,1524.73 h60
  text "IMM. TIN/SILVER OR EQUIV" at 9572.49,1387.42 h60
  text "OTHER" at 11003.94,1383.48 h60
  text "ARRAY/PANEL:" at 9232.94,1238.1 h60
  text "CUT AND TRIM PER M1 BOARD OUTLINE" at 10293.95,1229.88 h60
  text "N.C. ROUTE" at 10293.94,1093.91 h60
  text "X" at 10981.95,1093.91 h60
  text "V. SCORE" at 11159.94,1093.91 h60
  text "+/- 0.25mm" at 4247.12,1037.03 h60 r90
  text "CERTIFICATION:" at 9242.94,954.79 h60
  text "MATERIALS AND WORKMANSHIP FOR ALL PCBS" at 9967.94,954.79 h60
  text "TO MEET OR EXCEED THE REQUIREMENTS OF:" at 9967.94,860.72 h60
  text "X" at 9605.45,732.09 h60
  text "ANSI IPC-A-600F CLASS ->" at 9733.45,732.09 h60
  text "X" at 11381.45,732.09 h60
  text "2" at 11491.45,732.09 h60
  text "1" at 11176.45,730.6 h60
  text "3" at 11845.45,730.6 h60
  text "X" at 9876.51,590 h60
  text "REACH" at 10004.5,590 h60
  text "X" at 10417.45,584.41 h60
  text "RoHS" at 10545.45,584.41 h60
  text "OTHER" at 11189.85,584.41 h60
  text "PER ORDER" at 11586.91,584.41 h60
  text "ALL BOARDS MUST MEET OR EXCEED UL94-V0 REQUIREMENTS." at 9250.49,450.58 h60
  text "+/-" at -216,374.35 h60 r90
  text "PCB MUST BEAR THE UL94V-0 UL REGISTERED MATERIAL ID NUMBER" at 9250.49,334.52 h60
  text "0.25mm" at -126,266 h60 r90
  text "ADDITIONAL REQUIREMENTS:" at 9232.94,229.88 h60
  text "REQUIRED" at 11074.94,113.63 h60
  text "BARE BOARD ELEC. TEST:" at 9307.71,110.78 h60
  text "NONE" at 10613.45,110.78 h60
  text "X" at 10956.95,110.78 h60
  text "PER ORDER" at 11666.94,110.78 h60
  text "XX MIL VIAS REQUIRE NON-CONDUCTIVE FILL AND PLANARIZE" at 9475.86,-94.17 h59
  text "XX MIL VIAS REQUIRE CONDUCTIVE FILL AND PLANARIZE" at 9483.86,-198.14 h60
  text "+/- 0.25mm" at 1335.57,-293.22 h60
  text "OUTER XX MIL TRACES REQUIRE 50 OHM SINGLE-ENDED IMPEDANCE" at 9482.88,-361.53 h58
  text "LAYER 2 & 3 (INNER LAYERS) XX MIL WIDE, XX MIL SPACE / TRACES REQUIRE 100 OHM DIFFERENTIAL IMPEDANCE" at 9474.88,-597.24 h60
M11 Gerber Information:
  lines w10: -2385.9,-2442.75 4214.1,-2442.75 ; -2385.9,-2239.41 4216.1,-2239.41 ; -2385.9,-2036.08 -2385.9,-2646.08 1619.1,-2646.08 4216.1,-2646.08 4216.1,-2036.08 -2385.4,-2036.08 -2385.4,-2646.08 -809.9,-2646.08 ; 79.1,-2646.08 79.1,-2036.08 ; 1346.1,-2239.41 1346.1,-2036.08 ; 2186.1,-2239.41 2186.1,-2036.08 ; 2808.1,-2652.58 2808.1,-2449.75
  text "ALL ARTWORK VIEWED FROM TOP SIDE" at -2322.4,-2168.25 h60
  text "BOARD #:" at 154.1,-2168.25 h60
  text ".PRJ_Number" at 699.6,-2168.25 h60
  text "REV:" at 1544.1,-2168.25 h60
  text ".PCB_Rev" at 1835.6,-2168.25 h60
  text "SVN REV:" at 2382.1,-2168.25 h60
  text ".VersionControl_RevNumber" at 2888.1,-2168.25 h60
  text "LAYER NAME =" at -2322.4,-2371.07 h60
  text "TID #:" at 154.1,-2371.58 h60
  text ".TID" at 699.6,-2371.58 h60
  text "PLOT NAME =" at -2322.4,-2576.92 h60
  text ".plot_File_Name" at -1516.9,-2576.92 h60
  text "GENERATED    :" at 156.1,-2576.92 h60
  text ".Print_Date" at 1025.6,-2576.92 h60
  text ".Print_Time" at 1754.6,-2576.92 h60
  text "TEXAS INSTRUMENTS" at 3019.1,-2576.92 h60
M12 Stackup:
  drawing of 503 lines, arcs and shapes, not listed
  text "Layer" at 4410.88,6119.68 h60
  text "Name" at 4820.79,6119.68 h60
  text "Material" at 5750.54,6119.68 h60
  text "Thickness" at 6610.3,6119.68 h60
  text "Constant" at 7260.14,6119.68 h60
  text "Board Layer Stack" at 7830,6119.68 h60
  text "Top Overlay" at 4820.79,5999.68 h60
  text "Top Solder" at 4820.79,5879.68 h60
  text "Solder Resist" at 5750.54,5879.68 h60
  text "0.40mil" at 6610.3,5879.68 h60
  text "3.5" at 7260.14,5879.68 h60
  text "1" at 4410.88,5759.68 h60
  text "Top Layer" at 4820.79,5759.68 h60
  text "1.38mil" at 6610.3,5759.68 h60
  text "Dielectric 1" at 4820.79,5639.68 h60
  text "PP-006" at 5750.54,5639.68 h60
  text "7.17mil" at 6610.3,5639.68 h60
  text "4.1" at 7260.14,5639.68 h60
  text "2" at 4410.88,5519.68 h60
  text "Layer 1" at 4820.79,5519.68 h60
  text "CF-004" at 5750.54,5519.68 h60
  text "1.38mil" at 6610.3,5519.68 h60
  text "Dielectric 2" at 4820.79,5399.68 h60
  text "PP-006" at 5750.54,5399.68 h60
  text "7.17mil" at 6610.3,5399.68 h60
  text "4.1" at 7260.14,5399.68 h60
  text "3" at 4410.88,5279.68 h60
  text "Layer 2" at 4820.79,5279.68 h60
  text "CF-004" at 5750.54,5279.68 h60
  text "1.38mil" at 6610.3,5279.68 h60
  text "Dielectric 3" at 4820.79,5159.68 h60
  text "PP-006" at 5750.54,5159.68 h60
  text "7.17mil" at 6610.3,5159.68 h60
  text "4.1" at 7260.14,5159.68 h60
  text "4" at 4410.88,5039.68 h60
  text "Layer 3" at 4820.79,5039.68 h60
  text "1.38mil" at 6610.3,5039.68 h60
  text "Dielectric 4" at 4820.79,4919.68 h60
  text "FR-4" at 5750.54,4919.68 h60
  text "7.17mil" at 6610.3,4919.68 h60
  text "4.8" at 7260.14,4919.68 h60
  text "5" at 4410.88,4799.68 h60
  text "Layer 4" at 4820.79,4799.68 h60
  text "CF-004" at 5750.54,4799.68 h60
  text "1.38mil" at 6610.3,4799.68 h60
  text "Dielectric 5" at 4820.79,4679.68 h60
  text "PP-006" at 5750.54,4679.68 h60
  text "7.17mil" at 6610.3,4679.68 h60
  text "4.1" at 7260.14,4679.68 h60
  text "6" at 4410.88,4559.68 h60
  text "Layer 5" at 4820.79,4559.68 h60
  text "1.38mil" at 6610.3,4559.68 h60
  text "Dielectric 6" at 4820.79,4439.68 h60
  text "PP-006" at 5750.54,4439.68 h60
  text "7.17mil" at 6610.3,4439.68 h60
  text "4.1" at 7260.14,4439.68 h60
  text "7" at 4410.88,4319.68 h60
  text "Layer 6" at 4820.79,4319.68 h60
  text "CF-004" at 5750.54,4319.68 h60
  text "1.38mil" at 6610.3,4319.68 h60
  text "Dielectric 7" at 4820.79,4199.68 h60
  text "PP-006" at 5750.54,4199.68 h60
  text "7.17mil" at 6610.3,4199.68 h60
  text "4.1" at 7260.14,4199.68 h60
  text "8" at 4410.88,4079.68 h60
  text "Bottom Layer" at 4820.79,4079.68 h60
  text "1.38mil" at 6610.3,4079.68 h60
  text "Bottom Solder" at 4820.79,3959.68 h60
  text "Solder Resist" at 5750.54,3959.68 h60
  text "0.40mil" at 6610.3,3959.68 h60
  text "3.5" at 7260.14,3959.68 h60
  text "Bottom Overlay" at 4820.79,3839.68 h60
Drill Drawing:
  circle w10: c-2121.87,5202.62 r16.58
  circle w10: c-2121.87,5202.62 r27.63
  circle w10: c-2121.87,4332.38 r27.63
  lines w10: -2149.5,4194.25 -2135.69,4194.25 -2121.87,4180.44 -2108.06,4194.25 -2094.25,4194.25 -2108.06,4208.06 -2094.25,4221.88 -2108.06,4221.88 -2121.87,4235.69 -2135.69,4221.88 -2149.5,4221.88 -2135.69,4208.06 -2149.5,4194.25 ; -2149.5,4442.89 -2135.69,4442.89 -2135.69,4429.08 -2108.06,4429.08 -2108.06,4442.89 -2094.25,4442.89 -2094.25,4470.52 -2108.06,4470.52 -2108.06,4484.33 -2135.69,4484.33 -2135.69,4470.52 -2149.5,4470.52 -2149.5,4442.89 ; -2149.5,4581.02 -2121.87,4553.4 -2094.25,4581.02 -2121.87,4608.65 -2149.5,4581.02 ; -2149.5,4677.72 -2149.5,4691.53 -2135.69,4705.34 -2149.5,4719.16 -2149.5,4732.97 -2135.69,4732.97 -2121.87,4719.16 -2108.06,4732.97 -2094.25,4732.97 -2094.25,4719.16 -2108.06,4705.34 -2094.25,4691.53 -2094.25,4677.72 -2108.06,4677.72 -2121.87,4691.53 -2135.69,4677.72 -2149.5,4677.72 ; -2149.5,4802.04 -2094.25,4802.04 -2094.25,4857.29 -2149.5,4857.29 -2149.5,4802.04 ; -2149.5,4981.61 -2094.25,4981.61 -2121.87,4926.36 -2149.5,4981.61 ; -2149.5,5050.68 -2094.25,5050.68 -2094.25,5105.93 -2149.5,5105.93 -2149.5,5050.68 ; -2138.45,5061.73 -2105.3,5061.73 -2105.3,5094.88 -2138.45,5094.88 -2138.45,5061.73
  lines w12: -2199.59,4143.14 1031.9,4143.14 ; -2199.59,5262.02 1031.9,5262.02 ; -1861.73,4018.82 -1861.73,5386.34 ; -1529.73,4018.82 -1529.73,5386.34 ; -893.16,4018.82 -893.16,5386.34 ; -634.02,4018.82 -634.02,5386.34 ; -258.87,4018.82 -258.87,5386.34 ; 465.47,4018.82 465.47,5386.34 ; -2199.59,4018.82 1031.9,4018.82 1031.9,5386.34 -2199.59,5386.34 -2199.59,4018.82
  text "Symbol" at -2125,5299.32 h72
  text "Quantity" at -1824.43,5299.32 h72
  text "Finished Hole Size" at -1492.43,5299.32 h72
  text "Plated" at -855.87,5299.32 h72
  text "Hole Type" at -596.73,5299.32 h72
  text "Drill Layer Pair" at -221.57,5299.32 h72
  text "Hole Tolerance" at 502.76,5299.32 h72
  text "97" at -1824.43,5175 h60
  text "10.00mil (0.254mm)" at -1492.43,5175 h60
  text "PTH" at -855.87,5175 h60
  text "Round" at -596.73,5175 h60
  text "Top Layer - Bottom Layer" at -221.57,5175 h60
  text "15" at -1824.43,5050.68 h60
  text "11.81mil (0.300mm)" at -1492.43,5050.68 h60
  text "PTH" at -855.87,5050.68 h60
  text "Round" at -596.73,5050.68 h60
  text "Top Layer - Bottom Layer" at -221.57,5050.68 h60
  text "46" at -1824.43,4926.36 h60
  text "31.50mil (0.800mm)" at -1492.43,4926.36 h60
  text "PTH" at -855.87,4926.36 h60
  text "Round" at -596.73,4926.36 h60
  text "Top Layer - Bottom Layer" at -221.57,4926.36 h60
  text "10" at -1824.43,4802.04 h60
  text "40.00mil (1.016mm)" at -1492.43,4802.04 h60
  text "PTH" at -855.87,4802.04 h60
  text "Round" at -596.73,4802.04 h60
  text "Top Layer - Bottom Layer" at -221.57,4802.04 h60
  text "12" at -1824.43,4677.72 h60
  text "45.28mil (1.150mm)" at -1492.43,4677.72 h60
  text "PTH" at -855.87,4677.72 h60
  text "Round" at -596.73,4677.72 h60
  text "Top Layer - Bottom Layer" at -221.57,4677.72 h60
  text "4" at -1824.43,4553.4 h60
  text "51.18mil (1.300mm)" at -1492.43,4553.4 h60
  text "PTH" at -855.87,4553.4 h60
  text "Round" at -596.73,4553.4 h60
  text "Top Layer - Bottom Layer" at -221.57,4553.4 h60
  text "4" at -1824.43,4429.08 h60
  text "59.06mil (1.500mm)" at -1492.43,4429.08 h60
  text "PTH" at -855.87,4429.08 h60
  text "Round" at -596.73,4429.08 h60
  text "Top Layer - Bottom Layer" at -221.57,4429.08 h60
  text "16" at -1824.43,4304.76 h60
  text "62.99mil (1.600mm)" at -1492.43,4304.76 h60
  text "PTH" at -855.87,4304.76 h60
  text "Round" at -596.73,4304.76 h60
  text "Top Layer - Bottom Layer" at -221.57,4304.76 h60
  text "12" at -1824.43,4180.44 h60
  text "70.87mil (1.800mm)" at -1492.43,4180.44 h60
  text "PTH" at -855.87,4180.44 h60
  text "Round" at -596.73,4180.44 h60
  text "Top Layer - Bottom Layer" at -221.57,4180.44 h60
  text "216 Total" at -1824.43,4056.12 h60
Top Overlay 2:
  lines w10: 2950.25,952.52 3144.02,800.1 ; 2530,756.05 2881,755.85 2881,1534.68 2530,1534.68 2530,756.05 ; 3259.8,-28.88 3395.46,-28.72 3394.91,89.09 3289.8,89.09 3260.24,49.33 3259.8,-28.88 ; 3269.15,724.1 3404.81,724.26 3404.26,842.07 3299.15,842.07 3269.59,802.31 3269.15,724.1 ; 3271.52,323.66 3271.95,401.87 3301.52,441.63 3406.62,441.63 3407.17,323.82 3271.52,323.66
  text "TPS7A57 Parallel / LDO Solution" at 2383.37,-291.28 h60
Bottom Overlay 2:
  text "Ballast Resistor Size Comparison (20C rise)" at 3943.37,694.68 h40 r90
  text "2.5 miliohm" at 3640,275 h40 r90
  text "5 miliohm" at 3781.39,260 h40 r90
  text "5 ADC" at 3570,180 h40 r90
  text "Rballast" at 3623.37,-235.32 h40 r90
  text "2.5 miliohm" at 3693.37,-504.23 h40 r90
  text "5 miliohm" at 3833.36,-555.32 h40 r90
  text "2.5 ADC" at 3623.36,-580 h40 r90

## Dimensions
3253.64,1679.33 to 3775.3,1679.33 on M10 Fab Notes
1952.41,173.4 to 1283.21,695.05 on M10 Fab Notes
1288.29,1568.21 to 1288.29,2089.87 on M10 Fab Notes
0,0 to 3944.58,-1075.28 on M2 Board Dimensions
2243.17,3335.89 to 3950.94,3335.56 on M2 Board Dimensions
0.8,2262.93 to 2243.17,3335.89 on M2 Board Dimensions
3944.59,-1069.05 to 3953.12,3335.73 on M2 Board Dimensions
2236.81,-1075.32 to 3944.59,-1069.05 on M2 Board Dimensions
0.8,2262.93 to 2243.17,3335.89 on M2 Board Dimensions
0,0 to 0.8,2262.93 on M2 Board Dimensions
3773.55,1677.57 to 3773.55,1008.38 on M10 Fab Notes
1288.29,2086.94 to 1957.49,2086.94 on M10 Fab Notes
1952.41,176.33 to 1283.21,176.33 on M10 Fab Notes
-2093.9,-1912.58 to -1093.9,-1912.58 on M2 Board Dimensions
2236.81,-1075.32 to 0,0 on M2 Board Dimensions
0,0.24 to 2236.81,-1075.32 on M2 Board Dimensions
